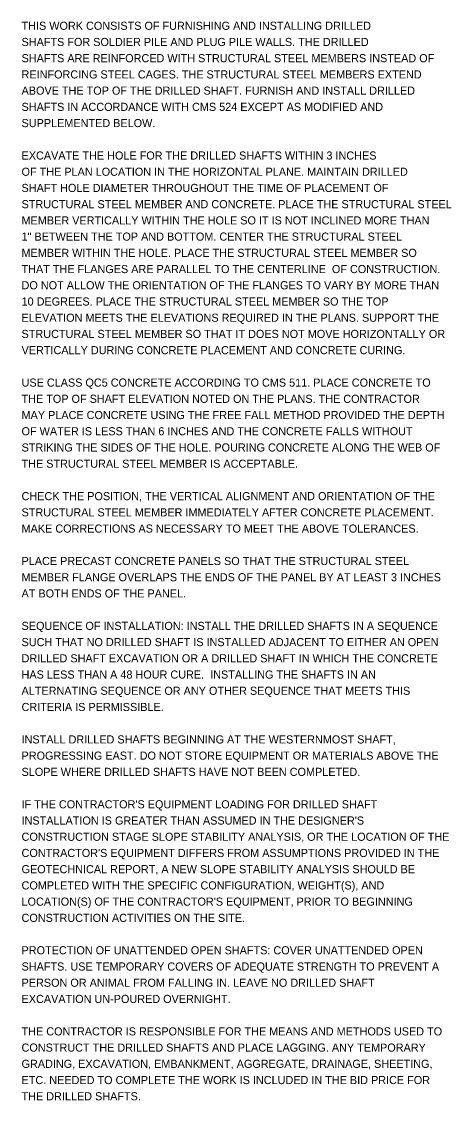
# Model space of a CAD drawing. Extents: x 0 to 51.2, y 0 to 22.
# Drawn here: x 43.82 to 51.24, y 1.68 to 20.3 of the extents above; entities that cross this region are included whole.
import ezdxf

# ---------------------------------------------------------------- set-up
doc = ezdxf.new("R2010")
doc.units = 0
doc.layers.add('TX_P_1', color=7, linetype='Continuous')

msp = doc.modelspace()

# ---------------------------------------------------------------- texts
at = {"layer": 'TX_P_1'}
for s, p in [('THIS WORK CONSISTS OF FURNISHING AND INSTALLING DRILLED', (43.82, 20.16)), ('SHAFTS FOR SOLDIER PILE AND PLUG PILE WALLS. THE DRILLED', (43.82, 19.88)), ('SHAFTS ARE REINFORCED WITH STRUCTURAL STEEL MEMBERS INSTEAD OF ', (43.82, 19.6)), ('REINFORCING STEEL CAGES. THE STRUCTURAL STEEL MEMBERS EXTEND ', (43.82, 19.32)), ('ABOVE THE TOP OF THE DRILLED SHAFT. FURNISH AND INSTALL DRILLED ', (43.82, 19.04)), ('SHAFTS IN ACCORDANCE WITH CMS 524 EXCEPT AS MODIFIED AND ', (43.82, 18.76)), ('SUPPLEMENTED BELOW.', (43.82, 18.48)), ('EXCAVATE THE HOLE FOR THE DRILLED SHAFTS WITHIN 3 INCHES', (43.82, 17.92)), ('OF THE PLAN LOCATION IN THE HORIZONTAL PLANE. MAINTAIN DRILLED ', (43.82, 17.64)), ('SHAFT HOLE DIAMETER THROUGHOUT THE TIME OF PLACEMENT OF ', (43.82, 17.36)), ('STRUCTURAL STEEL MEMBER AND CONCRETE. PLACE THE STRUCTURAL STEEL ', (43.82, 17.08)), ('MEMBER VERTICALLY WITHIN THE HOLE SO IT IS NOT INCLINED MORE THAN ', (43.82, 16.8)), ('1" BETWEEN THE TOP AND BOTTOM. CENTER THE STRUCTURAL STEEL ', (43.82, 16.52)), ('MEMBER WITHIN THE HOLE. PLACE THE STRUCTURAL STEEL MEMBER SO ', (43.82, 16.24)), ('THAT THE FLANGES ARE PARALLEL TO THE CENTERLINE  OF CONSTRUCTION. ', (43.82, 15.96)), ('DO NOT ALLOW THE ORIENTATION OF THE FLANGES TO VARY BY MORE THAN ', (43.82, 15.68)), ('10 DEGREES. PLACE THE STRUCTURAL STEEL MEMBER SO THE TOP ', (43.82, 15.4)), ('ELEVATION MEETS THE ELEVATIONS REQUIRED IN THE PLANS. SUPPORT THE ', (43.82, 15.12)), ('STRUCTURAL STEEL MEMBER SO THAT IT DOES NOT MOVE HORIZONTALLY OR ', (43.82, 14.84)), ('VERTICALLY DURING CONCRETE PLACEMENT AND CONCRETE CURING.', (43.82, 14.56)), ('USE CLASS QC5 CONCRETE ACCORDING TO CMS 511. PLACE CONCRETE TO ', (43.82, 14)), ('THE TOP OF SHAFT ELEVATION NOTED ON THE PLANS. THE CONTRACTOR ', (43.82, 13.72)), ('MAY PLACE CONCRETE USING THE FREE FALL METHOD PROVIDED THE DEPTH ', (43.82, 13.44)), ('OF WATER IS LESS THAN 6 INCHES AND THE CONCRETE FALLS WITHOUT ', (43.82, 13.16)), ('STRIKING THE SIDES OF THE HOLE. POURING CONCRETE ALONG THE WEB OF ', (43.82, 12.88)), ('THE STRUCTURAL STEEL MEMBER IS ACCEPTABLE.', (43.82, 12.6)), ('CHECK THE POSITION, THE VERTICAL ALIGNMENT AND ORIENTATION OF THE ', (43.82, 12.04)), ('STRUCTURAL STEEL MEMBER IMMEDIATELY AFTER CONCRETE PLACEMENT. ', (43.82, 11.76)), ('MAKE CORRECTIONS AS NECESSARY TO MEET THE ABOVE TOLERANCES.', (43.82, 11.48)), ('PLACE PRECAST CONCRETE PANELS SO THAT THE STRUCTURAL STEEL ', (43.82, 10.92)), ('MEMBER FLANGE OVERLAPS THE ENDS OF THE PANEL BY AT LEAST 3 INCHES ', (43.82, 10.64)), ('AT BOTH ENDS OF THE PANEL. ', (43.82, 10.36)), ('SEQUENCE OF INSTALLATION: INSTALL THE DRILLED SHAFTS IN A SEQUENCE ', (43.82, 9.8)), ('SUCH THAT NO DRILLED SHAFT IS INSTALLED ADJACENT TO EITHER AN OPEN ', (43.82, 9.52)), ('DRILLED SHAFT EXCAVATION OR A DRILLED SHAFT IN WHICH THE CONCRETE ', (43.82, 9.24)), ('HAS LESS THAN A 48 HOUR CURE.  INSTALLING THE SHAFTS IN AN ', (43.82, 8.96)), ('ALTERNATING SEQUENCE OR ANY OTHER SEQUENCE THAT MEETS THIS ', (43.82, 8.68)), ('CRITERIA IS PERMISSIBLE.', (43.82, 8.4)), ('INSTALL DRILLED SHAFTS BEGINNING AT THE WESTERNMOST SHAFT, ', (43.82, 7.84)), ('PROGRESSING EAST. DO NOT STORE EQUIPMENT OR MATERIALS ABOVE THE ', (43.82, 7.56)), ('SLOPE WHERE DRILLED SHAFTS HAVE NOT BEEN COMPLETED. ', (43.82, 7.28)), ("IF THE CONTRACTOR'S EQUIPMENT LOADING FOR DRILLED SHAFT ", (43.82, 6.72)), ("INSTALLATION IS GREATER THAN ASSUMED IN THE DESIGNER'S ", (43.82, 6.44)), ('CONSTRUCTION STAGE SLOPE STABILITY ANALYSIS, OR THE LOCATION OF THE ', (43.82, 6.16)), ("CONTRACTOR'S EQUIPMENT DIFFERS FROM ASSUMPTIONS PROVIDED IN THE ", (43.82, 5.88)), ('GEOTECHNICAL REPORT, A NEW SLOPE STABILITY ANALYSIS SHOULD BE ', (43.82, 5.6)), ('COMPLETED WITH THE SPECIFIC CONFIGURATION, WEIGHT(S), AND ', (43.82, 5.32)), ("LOCATION(S) OF THE CONTRACTOR'S EQUIPMENT, PRIOR TO BEGINNING ", (43.82, 5.04)), ('CONSTRUCTION ACTIVITIES ON THE SITE.', (43.82, 4.76)), ('PROTECTION OF UNATTENDED OPEN SHAFTS: COVER UNATTENDED OPEN ', (43.82, 4.2)), ('SHAFTS. USE TEMPORARY COVERS OF ADEQUATE STRENGTH TO PREVENT A ', (43.82, 3.92)), ('PERSON OR ANIMAL FROM FALLING IN. LEAVE NO DRILLED SHAFT ', (43.82, 3.64)), ('EXCAVATION UN-POURED OVERNIGHT.', (43.82, 3.36)), ('THE CONTRACTOR IS RESPONSIBLE FOR THE MEANS AND METHODS USED TO ', (43.82, 2.8)), ('CONSTRUCT THE DRILLED SHAFTS AND PLACE LAGGING. ANY TEMPORARY ', (43.82, 2.52)), ('GRADING, EXCAVATION, EMBANKMENT, AGGREGATE, DRAINAGE, SHEETING, ', (43.82, 2.24)), ('ETC. NEEDED TO COMPLETE THE WORK IS INCLUDED IN THE BID PRICE FOR ', (43.82, 1.96)), ('THE DRILLED SHAFTS. ', (43.82, 1.68))]:
    msp.add_text(s, height=0.14, dxfattribs=at).set_placement(p)

doc.saveas('drawing.dxf')
